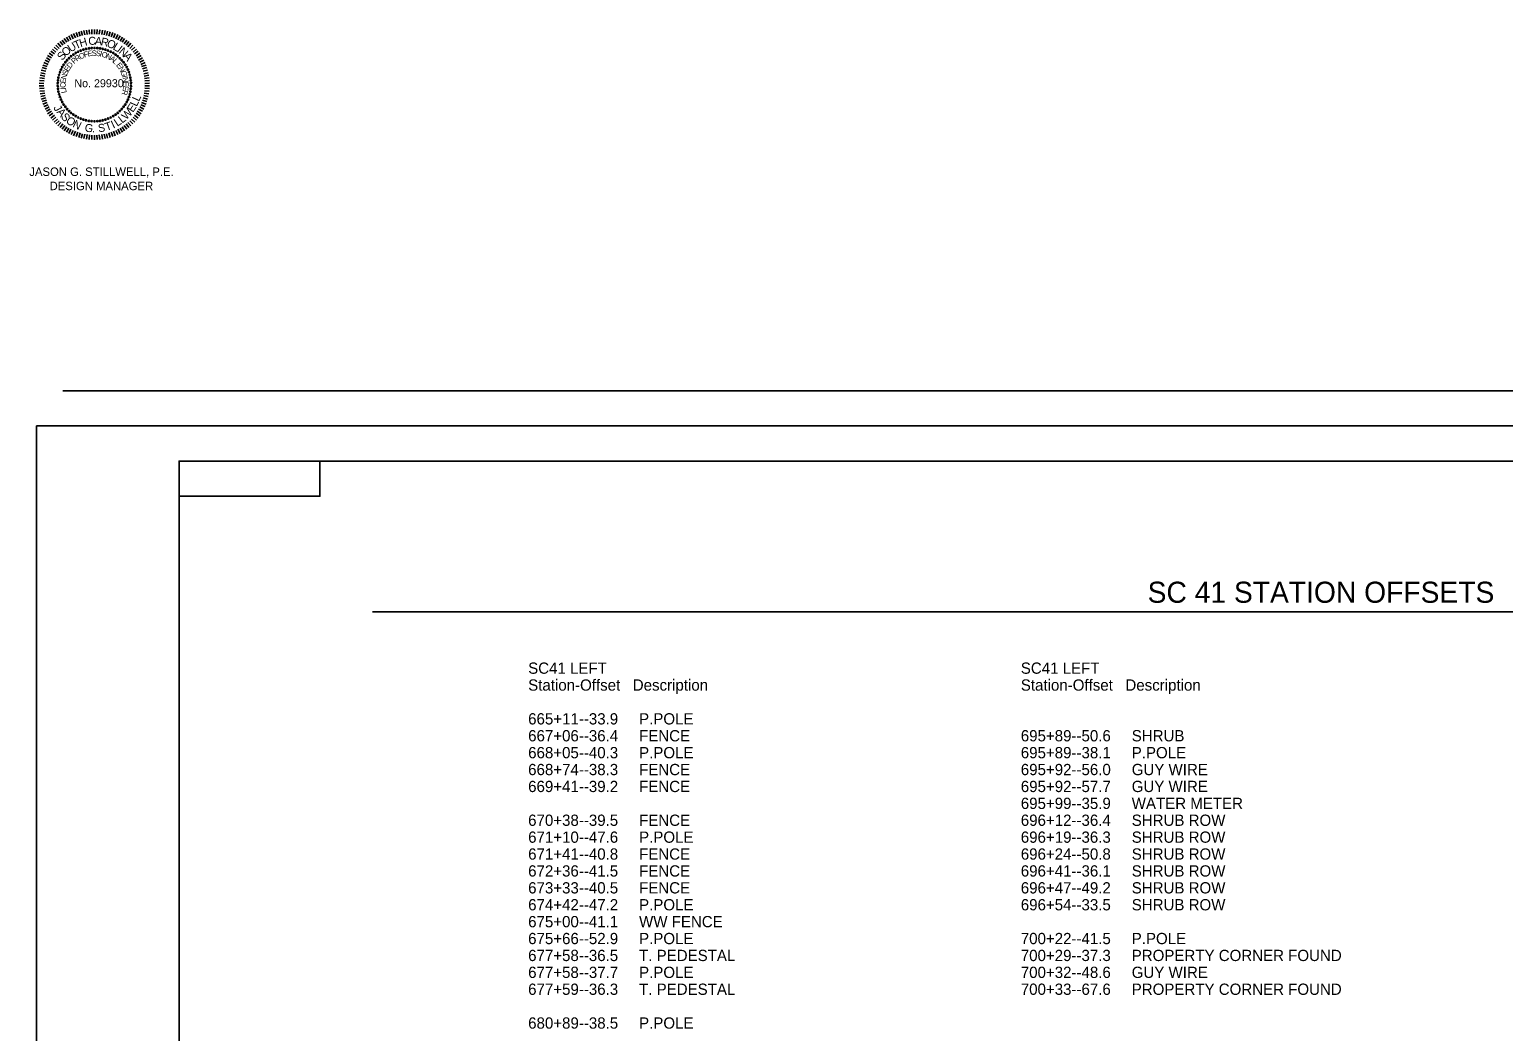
# Model space of a CAD drawing. Extents: x -13615 to 47191, y -1934 to 4415.
# Drawn here: x -10368 to -9321, y 2767 to 3478 of the extents above; entities that cross this region are included whole.
import ezdxf

# ---------------------------------------------------------------- set-up
doc = ezdxf.new("R2010")
doc.units = 0
for name, color, linetype in [('RD_SHT_Bndy', 7, 'Continuous'), ('RD_SHT_IplotShp', 7, 'Continuous'), ('RD_SHT_Snap', 7, 'Continuous'), ('RD_SHT_TX', 7, 'Continuous'), ('RD_TX_StaOff', 7, 'Continuous'), ('RD_TX_TitleSht', 7, 'Continuous')]:
    doc.layers.add(name, color=color, linetype=linetype)

# ---------------------------------------------------------------- blocks, each defined once
blk = doc.blocks.new('STILLWELL')
at = {"layer": 'RD_SHT_TX'}
for p, q in [((-19.7, 29.1), (-21.5, 31.8)), ((-18.2, 30), (-19.9, 32.8)), ((-16.7, 30.8), (-18.2, 33.7)), ((-15.1, 31.6), (-16.5, 34.6)), ((-13.6, 32.3), (-14.8, 35.3)), ((-11.9, 32.9), (-13, 36)), ((-10.3, 33.4), (-11.2, 36.6)), ((-8.6, 33.9), (-9.4, 37.1)), ((-6.9, 34.3), (-7.5, 37.5)), ((-5.2, 34.6), (-5.7, 37.8)), ((-3.5, 34.8), (-3.8, 38)), ((-1.8, 34.9), (-1.9, 38.2)), ((0, 34.9), (0, 38.2)), ((1.7, 34.9), (1.9, 38.2)), ((3.4, 34.8), (3.7, 38)), ((5.2, 34.6), (5.6, 37.8)), ((6.9, 34.3), (7.5, 37.5)), ((8.6, 33.9), (9.3, 37.1)), ((10.2, 33.4), (11.2, 36.6)), ((11.9, 32.9), (13, 36)), ((13.5, 32.3), (14.7, 35.3)), ((15.1, 31.6), (16.5, 34.6)), ((16.6, 30.8), (18.2, 33.7)), ((18.2, 30), (19.8, 32.8)), ((19.6, 29.1), (21.4, 31.8)), ((-29.5, 19.4), (-32.2, 21.3)), ((-28.5, 20.9), (-31.1, 22.8)), ((-27.4, 22.2), (-29.9, 24.3)), ((-26.3, 23.5), (-28.7, 25.7)), ((-25.1, 24.7), (-27.4, 27.1)), ((-23.8, 25.9), (-26, 28.4)), ((-22.5, 27), (-24.5, 29.6)), ((-21.1, 28.1), (-23, 30.7)), ((21.1, 28.1), (23, 30.7)), ((22.4, 27), (24.5, 29.6)), ((23.8, 25.9), (25.9, 28.4)), ((25, 24.7), (27.3, 27.1)), ((26.2, 23.5), (28.6, 25.7)), ((27.4, 22.2), (29.9, 24.3)), ((28.5, 20.9), (31.1, 22.8)), ((29.5, 19.4), (32.2, 21.3)), ((-34.1, 10.2), (-37.2, 11.2)), ((-33.6, 11.8), (-36.6, 12.9)), ((-32.9, 13.4), (-35.9, 14.7)), ((-32.2, 15), (-35.1, 16.4)), ((-31.4, 16.5), (-34.2, 18.1)), ((-30.5, 18), (-33.3, 19.7)), ((30.4, 18), (33.2, 19.7)), ((31.3, 16.5), (34.2, 18.1)), ((32.1, 15), (35.1, 16.4)), ((32.9, 13.4), (35.9, 14.7)), ((33.5, 11.8), (36.6, 12.9)), ((34.1, 10.2), (37.2, 11.2)), ((-35.9, -0.1), (-39.2, 0)), ((-35.8, 1.7), (-39.1, 1.9)), ((-35.6, 3.4), (-38.9, 3.8)), ((-35.4, 5.1), (-38.6, 5.7)), ((-35.1, 6.8), (-38.2, 7.5)), ((-34.6, 8.5), (-37.8, 9.4)), ((34.6, 8.5), (37.7, 9.4)), ((35, 6.8), (38.2, 7.5)), ((35.3, 5.1), (38.5, 5.7)), ((35.6, 3.4), (38.8, 3.8)), ((35.7, 1.7), (39, 1.9)), ((35.8, -0.1), (39.1, 0)), ((-35.9, -1.8), (-39.2, -1.9)), ((-35.8, -3.5), (-39.1, -3.8)), ((-35.6, -5.3), (-38.9, -5.6)), ((-35.4, -7), (-38.6, -7.5)), ((-35.1, -8.7), (-38.2, -9.4)), ((-34.6, -10.4), (-37.8, -11.2)), ((34.6, -10.4), (37.7, -11.2)), ((35, -8.7), (38.2, -9.4)), ((35.3, -7), (38.5, -7.5)), ((35.6, -5.3), (38.8, -5.6)), ((35.7, -3.5), (39, -3.8)), ((35.8, -1.8), (39.1, -1.9)), ((-34.1, -12), (-37.2, -13)), ((-33.6, -13.6), (-36.6, -14.8)), ((-32.9, -15.3), (-35.9, -16.6)), ((-32.2, -16.8), (-35.1, -18.3)), ((-31.4, -18.4), (-34.2, -19.9)), ((-30.5, -19.9), (-33.3, -21.6)), ((30.4, -19.9), (33.2, -21.6)), ((31.3, -18.4), (34.2, -19.9)), ((32.1, -16.8), (35.1, -18.3)), ((32.9, -15.3), (35.9, -16.6)), ((33.5, -13.6), (36.6, -14.8)), ((34.1, -12), (37.2, -13)), ((-29.5, -21.3), (-32.2, -23.2)), ((-28.5, -22.7), (-31.1, -24.7)), ((-27.4, -24.1), (-29.9, -26.2)), ((-26.3, -25.4), (-28.7, -27.6)), ((-25.1, -26.6), (-27.4, -28.9)), ((-23.8, -27.8), (-26, -30.2)), ((-22.5, -28.9), (-24.5, -31.4)), ((-21.1, -29.9), (-23, -32.6)), ((-19.7, -30.9), (-21.5, -33.7)), ((19.6, -30.9), (21.4, -33.7)), ((21.1, -29.9), (23, -32.6)), ((22.4, -28.9), (24.5, -31.4)), ((23.8, -27.8), (25.9, -30.2)), ((25, -26.6), (27.3, -28.9)), ((26.2, -25.4), (28.6, -27.6)), ((27.4, -24.1), (29.9, -26.2)), ((28.5, -22.7), (31.1, -24.7)), ((29.5, -21.3), (32.2, -23.2)), ((-18.2, -31.8), (-19.9, -34.7)), ((-16.7, -32.7), (-18.2, -35.6)), ((-15.1, -33.5), (-16.5, -36.4)), ((-13.6, -34.1), (-14.8, -37.2)), ((-11.9, -34.8), (-13, -37.8)), ((-10.3, -35.3), (-11.2, -38.4)), ((-8.6, -35.8), (-9.4, -38.9)), ((-6.9, -36.1), (-7.5, -39.3)), ((-5.2, -36.4), (-5.7, -39.7)), ((-3.5, -36.6), (-3.8, -39.9)), ((-1.8, -36.8), (-1.9, -40)), ((0, -36.8), (0, -40.1)), ((1.7, -36.8), (1.9, -40)), ((3.4, -36.6), (3.7, -39.9)), ((5.2, -36.4), (5.6, -39.7)), ((6.9, -36.1), (7.5, -39.3)), ((8.6, -35.8), (9.3, -38.9)), ((10.2, -35.3), (11.2, -38.4)), ((11.9, -34.8), (13, -37.8)), ((13.5, -34.1), (14.7, -37.2)), ((15.1, -33.5), (16.5, -36.4)), ((16.6, -32.7), (18.2, -35.6)), ((18.2, -31.8), (19.8, -34.7))]:
    blk.add_line(p, q, dxfattribs=at)
for centre in [(-13.3, 21.5), (-11.6, 22.4), (-9.8, 23.2), (-7.9, 23.9), (-6, 24.4), (-4, 24.8), (-2, 25), (0, 25.1), (2, 25), (3.9, 24.8), (5.9, 24.4), (7.8, 23.9), (9.7, 23.2), (11.5, 22.4), (13.3, 21.5), (-22.9, 11.5), (-21.9, 13.2), (-20.7, 14.9), (-19.5, 16.4), (-18.1, 17.8), (-16.6, 19.2), (-15, 20.4), (15, 20.4), (16.5, 19.2), (18, 17.8), (19.4, 16.4), (20.7, 14.9), (21.8, 13.2), (22.9, 11.5), (-26.1, 0.1), (-25.9, 2.1), (-25.6, 4), (-25.1, 6), (-24.5, 7.9), (-23.8, 9.7), (23.7, 9.7), (24.5, 7.9), (25.1, 6), (25.5, 4), (25.8, 2.1), (26, 0.1), (-26.1, -1.9), (-25.9, -3.9), (-25.6, -5.9), (-25.1, -7.8), (-24.5, -9.7), (24.5, -9.7), (25.1, -7.8), (25.5, -5.9), (25.8, -3.9), (26, -1.9), (-23.8, -11.6), (-22.9, -13.4), (-21.9, -15.1), (-20.7, -16.7), (-19.5, -18.3), (-18.1, -19.7), (-16.6, -21), (16.5, -21), (18, -19.7), (19.4, -18.3), (20.7, -16.7), (21.8, -15.1), (22.9, -13.4), (23.7, -11.6), (-15, -22.2), (-13.3, -23.3), (-11.6, -24.3), (-9.8, -25.1), (-7.9, -25.8), (-6, -26.3), (-4, -26.7), (-2, -26.9), (0, -27), (2, -26.9), (3.9, -26.7), (5.9, -26.3), (7.8, -25.8), (9.7, -25.1), (11.5, -24.3), (13.3, -23.3), (15, -22.2)]:
    blk.add_circle(centre, 0.49, dxfattribs=at)
for s, height, rotation, p in [('H', 5.68, 16.1357, (-9.9, 25.6)), ('C', 5.68, 4.076, (-4.2, 27.1)), ('A', 5.68, 355.3651, (0.1, 27.4)), ('R', 5.68, 347.3188, (4.1, 27.1)), ('S', 5.68, 49.6435, (-22.9, 15.8)), ('O', 5.68, 41.5972, (-20.4, 18.8)), ('U', 5.68, 32.2152, (-16.9, 21.8)), ('T', 5.68, 23.5044, (-13.2, 24.1)), ('O', 3.92, 24.9735, (-10, 16.9)), ('F', 3.92, 15.9995, (-7.1, 18.3)), ('E', 3.92, 8.9511, (-4.7, 19)), ('S', 3.92, 1.2546, (-1.9, 19.4)), ('S', 3.92, 353.558, (0.8, 19.5)), ('I', 3.92, 345.8615, (3.5, 19.2)), ('O', 3.92, 342.6583, (4.7, 19)), ('N', 3.92, 333.6842, (7.7, 18)), ('O', 5.68, 338.6079, (8.3, 26.2)), ('L', 5.68, 329.226, (12.6, 24.4)), ('I', 5.68, 322.5218, (15.5, 22.8)), ('N', 5.68, 319.1729, (16.8, 21.8)), ('A', 5.68, 310.4621, (20.1, 19)), ('E', 3.92, 60.2341, (-18.5, 7.9)), ('D', 3.92, 52.5376, (-17.1, 10.3)), ('P', 3.92, 41.0022, (-14.5, 13.5)), ('R', 3.92, 33.3057, (-12.5, 15.3)), ('A', 3.92, 325.3521, (10.4, 16.7)), ('L', 3.92, 317.6555, (12.6, 15.1)), ('E', 3.92, 308.0396, (15.1, 12.8)), ('N', 3.92, 300.343, (16.8, 10.6)), ('C', 3.92, 92.2915, (-20.4, -3.2)), ('E', 3.92, 83.9594, (-20.5, -0.2)), ('N', 3.92, 76.2628, (-20.2, 2.5)), ('S', 3.92, 67.9307, (-19.5, 5.4)), ('G', 3.92, 292.0109, (18.3, 8.1)), ('I', 3.92, 283.0368, (19.5, 5.1)), ('N', 3.92, 279.8336, (19.8, 4)), ('E', 3.92, 271.5014, (20.3, 1.1)), ('I', 3.92, 95.4947, (-20.2, -4.3)), ('L', 3.92, 101.9075, (-19.7, -6.6)), ('R', 3.92, 256.1083, (20.1, -4.4)), ('E', 3.92, 263.8049, (20.4, -1.7)), ('L', 5.68, 65.098, (31.6, -13.3)), ('J', 5.68, 299.033, (-29.4, -17.3)), ('A', 5.68, 310.5887, (-27.2, -20.6)), ('W', 5.68, 47.0518, (22.6, -26.4)), ('E', 5.68, 56.4327, (27.3, -21.1)), ('L', 5.68, 65.098, (30, -16.9)), ('S', 5.68, 310.5887, (-24.3, -24)), ('O', 5.68, 321.0072, (-20.8, -27.4)), ('N', 5.68, 333.4326, (-16, -30.8)), ('G', 5.68, 352.2045, (-7.2, -34.2)), ('S', 5.68, 8.0826, (2.9, -34.8)), ('T', 5.68, 18.9019, (8.5, -33.9)), ('I', 5.68, 25.3991, (13.3, -32.2)), ('L', 5.68, 34.0644, (16.2, -30.9)), ('L', 5.68, 37.6708, (19.6, -28.7)), ('.', 5.68, 0.8698, (-1.8, -34.9))]:
    blk.add_text(s, height=height, rotation=rotation, dxfattribs=at).set_placement(p)
blk.add_text('No. 29930', height=5.68, dxfattribs=at).set_placement((-14.3, -2.8))

msp = doc.modelspace()

# ---------------------------------------------------------------- linework, layer by layer
at = {"layer": 'RD_SHT_Bndy'}
for p, q in [((-8584.1, 3221.6), (-10344.1, 3221.6)), ((-8584.1, 3196.6), (-10344.1, 3196.6)), ((-8586.5, 3171.6), (-10261.5, 3171.6)), ((-10261.5, 3171.6), (-10261.5, 2121.6)), ((-10124, 3064.6), (-8724, 3064.6))]:
    msp.add_line(p, q, dxfattribs=at)
msp.add_lwpolyline([(-10261.5, 3146.6), (-10261.5, 3171.6), (-10161.5, 3171.6), (-10161.5, 3146.6)], close=True, dxfattribs=at)
at = {"layer": 'RD_SHT_IplotShp'}
msp.add_lwpolyline([(-10362.7, 3196.6), (-8566.7, 3196.6), (-8566.7, 2096.6), (-10362.7, 2096.6)], close=True, dxfattribs=at)
at = {"layer": 'RD_SHT_Snap'}
msp.add_line((-10362.7, 2096.6), (-10362.7, 3196.6), dxfattribs=at)

# ---------------------------------------------------------------- block references
at = {"layer": 'RD_SHT_TX'}
msp.add_blockref('STILLWELL', (-10321.6, 3439.9), dxfattribs=at)

# ---------------------------------------------------------------- texts
at = {"layer": 'RD_TX_StaOff'}
for s, height, p in [('SC 41 STATION OFFSETS', 15, (-9573.4, 3071)), ('SC41 LEFT', 8, (-10013.5, 3020.6)), ('SC41 LEFT', 8, (-9663.5, 3020.6)), ('Station-Offset   Description', 8, (-10013.5, 3008.6)), ('Station-Offset   Description', 8, (-9663.5, 3008.6)), ('665+11--33.9     P.POLE', 8, (-10013.5, 2984.6)), ('667+06--36.4     FENCE', 8, (-10013.5, 2972.6)), ('695+89--50.6     SHRUB', 8, (-9663.5, 2972.6)), ('668+05--40.3     P.POLE', 8, (-10013.5, 2960.6)), ('695+89--38.1     P.POLE', 8, (-9663.5, 2960.6)), ('668+74--38.3     FENCE', 8, (-10013.5, 2948.6)), ('695+92--56.0     GUY WIRE', 8, (-9663.5, 2948.6)), ('669+41--39.2     FENCE', 8, (-10013.5, 2936.6)), ('695+92--57.7     GUY WIRE', 8, (-9663.5, 2936.6)), ('695+99--35.9     WATER METER', 8, (-9663.5, 2924.6)), ('670+38--39.5     FENCE', 8, (-10013.5, 2912.6)), ('696+12--36.4     SHRUB ROW', 8, (-9663.5, 2912.6)), ('671+10--47.6     P.POLE', 8, (-10013.5, 2900.6)), ('696+19--36.3     SHRUB ROW', 8, (-9663.5, 2900.6)), ('671+41--40.8     FENCE', 8, (-10013.5, 2888.6)), ('696+24--50.8     SHRUB ROW', 8, (-9663.5, 2888.6)), ('672+36--41.5     FENCE', 8, (-10013.5, 2876.6)), ('696+41--36.1     SHRUB ROW', 8, (-9663.5, 2876.6)), ('673+33--40.5     FENCE', 8, (-10013.5, 2864.6)), ('696+47--49.2     SHRUB ROW', 8, (-9663.5, 2864.6)), ('674+42--47.2     P.POLE', 8, (-10013.5, 2852.6)), ('696+54--33.5     SHRUB ROW', 8, (-9663.5, 2852.6)), ('675+00--41.1     WW FENCE', 8, (-10013.5, 2840.6)), ('675+66--52.9     P.POLE', 8, (-10013.5, 2828.6)), ('700+22--41.5     P.POLE', 8, (-9663.5, 2828.6)), ('677+58--36.5     T. PEDESTAL', 8, (-10013.5, 2816.6)), ('700+29--37.3     PROPERTY CORNER FOUND', 8, (-9663.5, 2816.6)), ('677+58--37.7     P.POLE', 8, (-10013.5, 2804.6)), ('700+32--48.6     GUY WIRE', 8, (-9663.5, 2804.6)), ('677+59--36.3     T. PEDESTAL', 8, (-10013.5, 2792.6)), ('700+33--67.6     PROPERTY CORNER FOUND', 8, (-9663.5, 2792.6)), ('680+89--38.5     P.POLE', 8, (-10013.5, 2768.6))]:
    msp.add_text(s, height=height, dxfattribs=at).set_placement(p)
at = {"layer": 'RD_TX_TitleSht'}
for s, p in [('JASON G. STILLWELL, P.E.', (-10367.9, 3374.1)), ('DESIGN MANAGER', (-10353.5, 3364))]:
    msp.add_text(s, height=6, dxfattribs=at).set_placement(p)

doc.saveas('drawing.dxf')
